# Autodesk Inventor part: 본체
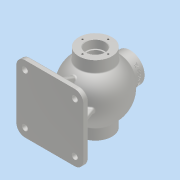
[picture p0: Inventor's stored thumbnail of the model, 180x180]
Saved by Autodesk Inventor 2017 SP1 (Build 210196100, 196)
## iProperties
Part Number: 본체
Material: 알루미늄 6061
Document SubType Name: Modeling
Designer: MRC
Density: 2.7 g/cm^3
Appearance: 알루미늄 - 평지
Mass: 1526.73 g
Surface Area: 1173.98 cm^2
Volume: 565.456 cm^3
Author: MRC
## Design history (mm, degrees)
sketch "스케치1"
  geometry: L1 (0, 65)-(0, -65); L2 (0, 65)-(31, 65); L3 (31, -65)-(0, -65); L4 (31, 65)-(31, 44.215); L5 (31, -44.215)-(31, -65); A1 r 54 centre (0, 0) between (31, -44.215) and (31, 44.215); A2 r 44 centre (0, 0) between (0, -44) and (0, 44); 2 further points
  constraints: 10 end point, 4 coincident, 4 perpendicular, 4 point on circle, 2 centre point, 2 point on line, 1 horizontal, 1 midpoint, 1 vertical
  dimensions: "d1" = 130 distance of L1.start L1.end; "d2" = 108 diameter of A1; "d4" = 62 diameter of L4 L1; "d5" = 62 diameter of L5 L1; "d6" = 88 diameter of A2
revolve "회전1" sketch "스케치1" stored, may be unused: angle "d7" = 90 deg
node "작업 평면1"
sketch "스케치2"
  geometry: C1 r 27 at (0, 0); 1 further point
  constraints: 1 centre point, 1 coincident
  dimensions: "d9" = 54 diameter of C1
extrude "돌출1" join sketch "스케치2" stored distance "d10" = 10; taper "d11" = 0 deg
sketch "스케치4"
  geometry: C1 r 31 at (0, 0) reference; C2 r 17.5 at (0, 0)
  constraints: 1 centre point, 1 coincident
  dimensions: "d12" = 35 diameter of C2
extrude "돌출2" cut sketch "스케치4" distance "d13" = 16; taper "d14" = 0 deg
sketch "스케치5"
  geometry: C1 r 17.5 at (0, 0) reference; C2 r 15 at (0, 0)
  constraints: 1 centre point, 1 coincident
  dimensions: "d15" = 30 diameter of C2
extrude "돌출3" cut sketch "스케치5" stored distance "d16" = 16; taper "d17" = 0 deg
sketch "스케치6"
  geometry: C1 r 31 at (0, 0) reference; C2 r 17.5 at (0, 0)
  constraints: 1 centre point, 1 coincident
  dimensions: "d18" = 35 diameter of C2
extrude "돌출4" cut sketch "스케치6" distance "d19" = 16; taper "d20" = 0 deg
sketch "스케치7"
  geometry: C1 r 17.5 at (0, 0) reference; C2 r 15 at (0, 0)
  constraints: 1 centre point, 1 coincident
  dimensions: "d21" = 30 diameter of C2
extrude "돌출5" cut sketch "스케치7" stored distance "d22" = 16; taper "d23" = 0 deg
sketch "스케치8"
  geometry: C1 r 27 at (0, 0) reference; C2 r 13 at (0, 0)
  constraints: 1 centre point, 1 coincident
  dimensions: "d24" = 26 diameter of C2
extrude "돌출6" cut sketch "스케치8" stored distance "d25" = 16; taper "d26" = 0 deg
sketch "스케치9"
  geometry: C1 r 17.5 at (0, 0) reference; 1 further point
  constraints: 1 vertical alignment
  dimensions: "d27" = 24 distance of point (0, 24) C1.centre
hole "구멍1" sketch "스케치9" at (0, 24) diameter "d28" = 3.242; stored, may be unused: countersink angle "d32" = 90 deg, drill point angle "d34" = 118 deg; dims "d29" = 12, "d30" = 4, "d31" = 2, "d33" = 15
sketch "스케치10"
  geometry: C1 r 13 at (0, 0) reference; 1 further point
  constraints: 1 vertical alignment
  dimensions: "d38" = 20 distance of C1.centre point (0, 20)
hole "구멍2" sketch "스케치10" at (0, 20) diameter "d39" = 3.242; stored, may be unused: countersink angle "d43" = 90 deg, drill point angle "d45" = 118 deg; dims "d40" = 9, "d41" = 4, "d42" = 2, "d44" = 11
node "작업 평면2"
sketch "스케치11"
  geometry: L1 (62.5, -62.5)-(-62.5, -62.5); L2 (-62.5, -62.5)-(-62.5, 62.5); L3 (-62.5, 62.5)-(62.5, 62.5); L4 (62.5, 62.5)-(62.5, -62.5); L5 (62.5, -62.5)-(-62.5, 62.5); L6 (-62.5, -62.5)-(62.5, 62.5); 1 further point
  constraints: 12 end point, 2 midpoint, 2 parallel, 1 horizontal, 1 perpendicular
  dimensions: "d50" = 125 distance of L1.start L1.end; "d51" = 125 distance of L1.end L2.end
extrude "돌출7" join sketch "스케치11" distance "d52" = 10; taper "d53" = 0 deg
fillet "모깎기1" dims "d54" = 16
sketch "스케치13"
  geometry: L1 (-39.345, -44.351)-(-50.5, -75); L2 (40.483, -47.479)-(50.5, -75); L3 (-27, 46.765)-(-27, 65) reference; L4 (-27, 65)-(-21.621, 65) reference; L5 (-21.621, 65)-(-21.621, 54) reference; L6 (-21.621, 54)-(-20, 53.026) reference; L7 (-20, 53.026)-(-18.379, 54) reference; L8 (-18.379, 54)-(-18.379, 65) reference; L9 (-18.379, 65)-(-13, 65) reference; L10 (-13, 65)-(-13, 42.036) reference; L11 (13, 42.036)-(13, 65) reference; L12 (13, 65)-(18.379, 65) reference; L13 (18.379, 65)-(18.379, 54) reference; L14 (18.379, 54)-(20, 53.026) reference; L15 (20, 53.026)-(21.621, 54) reference; L16 (21.621, 54)-(21.621, 65) reference; L17 (21.621, 65)-(27, 65) reference; L18 (27, 65)-(27, 46.765) reference; L19 (62.5, -75)-(62.5, -85) reference; L20 (62.5, -85)-(-62.5, -85) reference; L21 (-62.5, -85)-(-62.5, -75) reference; L22 (-62.5, -75)-(62.5, -75) reference; A1 r 54 centre (0, 0) between (-27, 46.765) and (27, 46.765) reference; A2 r 44 centre (0, 0) between (-13, 42.036) and (13, 42.036) reference; 1 further point
  constraints: 4 end point, 2 point on line
  dimensions: "d55" = 110 deg angle of L1 L22; "d56" = 110 deg angle of L22 L2; "d57" = 12 distance of L2.end L19.start; "d58" = 12 distance of L21.end L1.end
  node "절단 모서리 투영1"
feature "리브1" dims "d59" = 20, "d60" = 8, "d61" = 0, "d62" = 0, "d63" = 1, "d64" = 1
feature "리브2" dims "d65" = 20, "d66" = 8, "d67" = 0, "d68" = 0, "d69" = 1, "d70" = 1
sketch "스케치14"
  geometry: L1 (17.5, -65)-(17.5, -49) reference; L2 (17.5, -49)-(15, -49) reference; L3 (15, -49)-(15, -41.364) reference; L4 (42.036, -13)-(65, -13) reference; L5 (65, -13)-(65, -18.379) reference; L6 (65, -18.379)-(54, -18.379) reference; L7 (54, -18.379)-(53.026, -20) reference; L8 (53.026, -20)-(54, -21.621) reference; L9 (54, -21.621)-(65, -21.621) reference; L10 (65, -21.621)-(65, -27) reference; L11 (65, -27)-(46.765, -27) reference; L12 (31, -44.215)-(31, -65) reference; L13 (31, -65)-(25.621, -65) reference; L14 (25.621, -65)-(25.621, -50) reference; L15 (25.621, -50)-(24, -49.026) reference; L16 (24, -49.026)-(22.379, -50) reference; L17 (22.379, -50)-(22.379, -65) reference; L18 (22.379, -65)-(17.5, -65) reference; L19 (17.5, 49)-(17.5, 65) reference; L20 (17.5, 65)-(22.379, 65) reference; L21 (22.379, 65)-(22.379, 50) reference; L22 (22.379, 50)-(24, 49.026) reference; L23 (24, 49.026)-(25.621, 50) reference; L24 (25.621, 50)-(25.621, 65) reference; L25 (25.621, 65)-(31, 65) reference; L26 (31, 65)-(31, 44.215) reference; L27 (46.765, 27)-(65, 27) reference; L28 (65, 27)-(65, 21.621) reference; L29 (65, 21.621)-(54, 21.621) reference; L30 (54, 21.621)-(53.026, 20) reference; L31 (53.026, 20)-(54, 18.379) reference; L32 (54, 18.379)-(65, 18.379) reference; L33 (65, 18.379)-(65, 13) reference; L34 (65, 13)-(42.036, 13) reference; L35 (15, 41.364)-(15, 49) reference; L36 (15, 49)-(17.5, 49) reference; L37 (-17.5, 65)-(-17.5, 49) reference; L38 (-17.5, 49)-(-15, 49) reference; L39 (-15, 49)-(-15, 41.364) reference; L40 (-15, -41.364)-(-15, -49) reference; L41 (-15, -49)-(-17.5, -49) reference; L42 (-17.5, -49)-(-17.5, -65) reference; L43 (-17.5, -65)-(-22.379, -65) reference; L44 (-22.379, -65)-(-22.379, -50) reference; L45 (-22.379, -50)-(-24, -49.026) reference; L46 (-24, -49.026)-(-25.621, -50) reference; L47 (-25.621, -50)-(-25.621, -65) reference; L48 (-25.621, -65)-(-31, -65) reference; L49 (-31, -65)-(-31, -44.215) reference; L50 (-53.852, -4)-(-75, -4) reference; L51 (-75, -4)-(-75, -62.5) reference; L52 (-75, -62.5)-(-85, -62.5) reference; L53 (-85, -62.5)-(-85, 62.5) reference; L54 (-85, 62.5)-(-75, 62.5) reference; L55 (-75, 62.5)-(-75, 4) reference; L56 (-75, 4)-(-53.852, 4) reference; L57 (-31, 44.215)-(-31, 65) reference; L58 (-31, 65)-(-25.621, 65) reference; L59 (-25.621, 65)-(-25.621, 50) reference; L60 (-25.621, 50)-(-24, 49.026) reference; L61 (-24, 49.026)-(-22.379, 50) reference; L62 (-22.379, 50)-(-22.379, 65) reference; L63 (-22.379, 65)-(-17.5, 65) reference; L64 (-57.314, -44.063)-(-75, -50.5)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; A1 r 44 centre (0, 0) between (15, -41.364) and (42.036, -13) reference; A2 r 54 centre (0, 0) between (31, -44.215) and (46.765, -27) reference; A3 r 54 centre (0, 0) between (46.765, 27) and (31, 44.215) reference; A4 r 44 centre (0, 0) between (42.036, 13) and (15, 41.364) reference; A5 r 44 centre (0, 0) between (-15, 41.364) and (-15, -41.364) reference; A6 r 54 centre (0, 0) between (-53.852, -4) and (-31, -44.215) reference; A7 r 54 centre (0, 0) between (-31, 44.215) and (-53.852, 4) reference; 1 further point
  constraints: 4 end point, 2 point on line
  dimensions: "d71" = 110 deg angle of L51 L64; "d72" = 110 deg angle of L55 L65; "d73" = 12 distance of L65.end L54.end; "d74" = 12 distance of L51.end L64.end
  node "절단 모서리 투영2"
feature "리브3" dims "d75" = 20, "d76" = 8, "d77" = 0, "d78" = 0, "d79" = 1, "d80" = 1
feature "리브4" dims "d81" = 20, "d82" = 8, "d83" = 0, "d84" = 0, "d85" = 1, "d86" = 1
sketch "스케치15"
  geometry: C1 r 5.5 at (-46.5, 46.5); C2 r 5.5 at (46.5, 46.5); C3 r 5.5 at (46.5, -46.5); C4 r 5.5 at (-46.5, -46.5); A1 r 16 centre (-46.5, 46.5) between (-46.5, 62.5) and (-62.5, 46.5) reference; A2 r 16 centre (-46.5, -46.5) between (-62.5, -46.5) and (-46.5, -62.5) reference; A3 r 16 centre (46.5, -46.5) between (46.5, -62.5) and (62.5, -46.5) reference; A4 r 16 centre (46.5, 46.5) between (62.5, 46.5) and (46.5, 62.5) reference; 1 further point
  constraints: 4 centre point, 4 coincident
  dimensions: "d87" = 11 diameter of C1; "d88" = 11 diameter of C2; "d89" = 11 diameter of C3; "d90" = 11 diameter of C4
extrude "돌출8" cut sketch "스케치15" stored distance "d91" = 10; taper "d92" = 0 deg
fillet "모깎기2" dims "d93" = 3
fillet "모깎기3" dims "d94" = 3
fillet "모깎기4" dims "d95" = 3
fillet "모깎기5" dims "d96" = 3
chamfer "모따기1" distance "d97" = 1; stored, may be unused: second distance "d98" = 2, angle "d99" = 45 deg
fillet "모깎기6" dims "d100" = 0.6
fillet "모깎기7" dims "d101" = 0.6
fillet "모깎기8" dims "d102" = 3
fillet "모깎기9" dims "d103" = 3
node "작업 평면3"
sketch "스케치16"
  geometry: L1 (65, 27)-(65, -27) reference; 2 further points
  constraints: 1 horizontal alignment, 1 other
  dimensions: "d105" = 9 distance from line of L1 point (56, 0)
feature "엠보싱1" sketch "스케치16" dims "d1" = 130, "d2" = 108, "d4" = 62, "d5" = 62, "d6" = 88, "d12" = 35, "d106" = 0.5, "d107" = 0
node "솔리드1"
pattern_circular "원형 패턴1" dims angle "d36" = 360 deg
mirror "미러1"
pattern_circular "원형 패턴2" dims angle "d47" = 360 deg
other parameters: "d3" = 62, "d8" = 65, "d49" = -85, "d104" = 27
